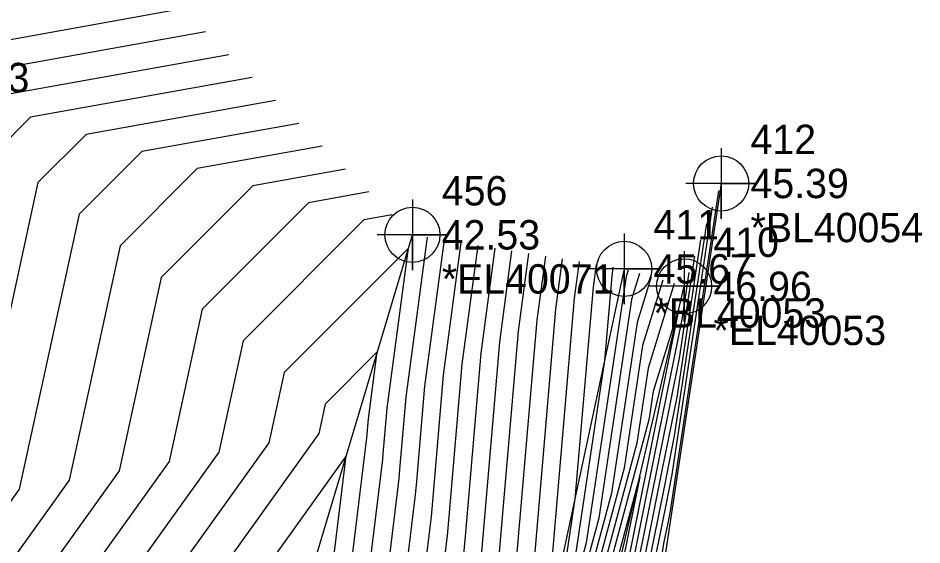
# Model space of a CAD drawing. Extents: x 2090860 to 2091277, y 159470 to 160080.
# Drawn here: x 2091069.7 to 2091146.6, y 159860.8 to 159905.6 of the extents above; entities that cross this region are included whole.
import ezdxf

# ---------------------------------------------------------------- set-up
doc = ezdxf.new("R2010")
doc.units = 0
for name, color, linetype in [('DTM Contours Major', 7, 'Continuous'), ('DTM Contours Minor', 7, 'Continuous'), ('Exist DTM Breakline', 7, 'Continuous'), ('Exist DTM Breakline Cogo Comment', 7, 'Continuous'), ('Exist DTM Breakline Cogo Elevation', 7, 'Continuous'), ('Exist DTM Breakline Cogo Number', 7, 'Continuous'), ('Exist DTM Breakline Cogo Point CELL', 7, 'Continuous'), ('Exist DTM Breakline Underwater', 7, 'Continuous'), ('Exist DTM Breakline Underwater Cogo Comment', 7, 'Continuous'), ('Exist DTM Breakline Underwater Cogo Elevation', 7, 'Continuous'), ('Exist DTM Breakline Underwater Cogo Number', 7, 'Continuous'), ('Exist DTM Breakline Underwater Cogo Point CELL', 7, 'Continuous'), ('Exist DTM Regular Point Cogo Elevation', 7, 'Continuous')]:
    doc.layers.add(name, color=color, linetype=linetype)

msp = doc.modelspace()

# ---------------------------------------------------------------- linework, layer by layer
at = {"layer": 'DTM Contours Major'}
for points in [[(2091083.646, 159906.422), (2091065.229, 159903.128), (2091061.167, 159901.876), (2091059.834, 159906.321), (2091038.544, 159901.84), (2091046.679, 159928.13)], [(2091091.582, 159898.637), (2091075.464, 159895.754), (2091071.361, 159891.649), (2091065.515, 159864.769), (2091059.162, 159855.905), (2091062.527, 159845.344), (2091062.382, 159844.528), (2091071.24, 159827.424), (2091068.468, 159817.052), (2091062.553, 159811.484), (2091060.259, 159801.479), (2091046.876, 159791.945), (2091037.586, 159782.801), (2091031.987, 159764.384), (2091026.688, 159760.214), (2091021.294, 159752.688), (2091014.874, 159747.469), (2091001.671, 159730.125), (2090998.416, 159727.263), (2090990.823, 159719.668), (2090976.25, 159706.989)], [(2091099.517, 159890.851), (2091094.379, 159889.932), (2091085.334, 159880.882), (2091082.516, 159867.927), (2091070.303, 159850.886), (2091072.441, 159844.175), (2091072.201, 159842.82), (2091077.78, 159832.047), (2091073.12, 159814.614), (2091069.924, 159811.606), (2091065.116, 159790.633), (2091059.844, 159786.877), (2091043.696, 159770.983), (2091041.123, 159762.521), (2091029.056, 159753.026), (2091026.145, 159748.964), (2091013.055, 159738.321), (2091004.963, 159727.692), (2091002.968, 159725.938), (2090989.66, 159712.626), (2090981.654, 159705.661)], [(2091122.565, 159883.928), (2091121.878, 159881.704), (2091119.096, 159863.114), (2091115.786, 159850.809), (2091115.429, 159848.821), (2091111.116, 159829.605), (2091110.193, 159820.456), (2091105.233, 159799.272), (2091103.435, 159793.012), (2091103.104, 159791.575), (2091106.385, 159784.178), (2091112.426, 159784.611), (2091120.155, 159785.157), (2091119.551, 159794.732), (2091119.607, 159802.178), (2091118.207, 159822.931), (2091118.9, 159830.534), (2091119.632, 159835.369), (2091122.895, 159856.915), (2091124.672, 159865.752), (2091125.548, 159870.109), (2091128.279, 159888.173)], [(2091105.922, 159886.774), (2091104.261, 159874.343), (2091103.538, 159865.895), (2091103.449, 159864.849), (2091101.246, 159846.776), (2091097.888, 159833.505), (2091097.32, 159832.37), (2091088.926, 159815.582), (2091086.283, 159805.672), (2091086.136, 159805.119), (2091075.366, 159785.296), (2091075.848, 159783.485), (2091075.953, 159781.891), (2091074.613, 159776.904)], [(2091111.672, 159885.85), (2091110.634, 159878.082), (2091109.134, 159860.552), (2091108.948, 159858.381), (2091107.858, 159849.436), (2091102.572, 159828.552), (2091102.265, 159827.937), (2091097.718, 159818.843), (2091092.826, 159800.504), (2091092.553, 159799.481), (2091086.279, 159787.931), (2091087.501, 159783.333), (2091087.769, 159779.288)], [(2091117.422, 159884.926), (2091117.008, 159881.82), (2091114.729, 159855.209), (2091114.539, 159852.984), (2091114.358, 159851.98), (2091113.72, 159849.137), (2091107.257, 159823.599), (2091107.21, 159823.504), (2091106.51, 159822.104), (2091099.37, 159795.336), (2091098.971, 159793.843), (2091097.192, 159790.566), (2091099.154, 159783.181), (2091099.586, 159776.685)], [(2091116.5, 159845.662), (2091116.642, 159846.45), (2091123.408, 159871.606), (2091123.751, 159873.9), (2091125.877, 159880.786), (2091124.096, 159871.932), (2091119.458, 159848.869), (2091118.165, 159840.333), (2091117.875, 159838.418), (2091116.082, 159818.747), (2091116.665, 159810.095), (2091116.541, 159793.591), (2091116.938, 159787.302), (2091111.861, 159786.943), (2091107.893, 159786.659), (2091105.739, 159791.517), (2091105.956, 159792.461), (2091110.673, 159808.884), (2091112.741, 159817.715), (2091114.792, 159838.05), (2091116.5, 159845.662)], [(2091097.594, 159868.402), (2091081.444, 159845.868), (2091082.356, 159843.007), (2091082.019, 159841.112), (2091084.319, 159836.671), (2091077.773, 159812.177), (2091077.295, 159811.727), (2091075.142, 159802.335), (2091079.718, 159810.758), (2091079.74, 159810.84), (2091080.135, 159812.321), (2091092.376, 159836.804), (2091093.203, 159838.459), (2091094.634, 159844.116), (2091097.594, 159868.402)]]:
    msp.add_lwpolyline(points, dxfattribs=at)
at = {"layer": 'DTM Contours Minor'}
for points in [[(2091085.63, 159904.476), (2091061.277, 159900.12), (2091060.882, 159899.725), (2091052.763, 159862.4), (2091050.806, 159859.669), (2091055.091, 159846.22), (2091055.018, 159845.809), (2091066.336, 159823.957), (2091064.979, 159818.88), (2091057.025, 159811.393), (2091056.616, 159809.613), (2091037.15, 159795.745), (2091033.004, 159791.665), (2091025.134, 159765.782), (2091024.911, 159765.606), (2091017.656, 159755.482), (2091016.238, 159754.329), (2090999.201, 159731.949), (2090995.001, 159728.257), (2090991.695, 159724.95), (2090972.197, 159707.986)], [(2091087.614, 159902.53), (2091066.006, 159898.665), (2091064.375, 159897.033), (2091057.014, 159863.189), (2091053.591, 159858.414), (2091057.57, 159845.928), (2091057.473, 159845.382), (2091067.971, 159825.113), (2091066.142, 159818.271), (2091058.867, 159811.424), (2091057.831, 159806.902), (2091040.392, 159794.478), (2091034.531, 159788.71), (2091027.419, 159765.316), (2091025.503, 159763.809), (2091018.868, 159754.551), (2091015.783, 159752.042), (2091000.024, 159731.341), (2090996.139, 159727.925), (2090991.404, 159723.189), (2090973.548, 159707.654)], [(2091089.598, 159900.583), (2091070.735, 159897.209), (2091067.868, 159894.341), (2091061.264, 159863.979), (2091056.377, 159857.16), (2091060.048, 159845.636), (2091059.927, 159844.955), (2091069.606, 159826.269), (2091067.305, 159817.661), (2091060.71, 159811.454), (2091059.045, 159804.19), (2091043.634, 159793.212), (2091036.059, 159785.755), (2091029.703, 159764.85), (2091026.095, 159762.012), (2091020.081, 159753.62), (2091015.328, 159749.755), (2091000.847, 159730.733), (2090997.277, 159727.594), (2090991.114, 159721.429), (2090974.899, 159707.322)], [(2091093.566, 159896.69), (2091080.192, 159894.298), (2091074.854, 159888.957), (2091069.765, 159865.558), (2091061.947, 159854.65), (2091065.005, 159845.052), (2091064.837, 159844.101), (2091072.875, 159828.58), (2091069.631, 159816.443), (2091064.396, 159811.515), (2091061.473, 159798.767), (2091050.118, 159790.678), (2091039.113, 159779.846), (2091034.271, 159763.918), (2091027.28, 159758.417), (2091022.507, 159751.757), (2091014.419, 159745.182), (2091002.494, 159729.516), (2090999.554, 159726.932), (2090990.532, 159717.907), (2090977.601, 159706.657)], [(2091095.549, 159894.744), (2091084.921, 159892.843), (2091078.348, 159886.266), (2091074.015, 159866.348), (2091064.733, 159853.396), (2091067.484, 159844.76), (2091067.291, 159843.674), (2091074.51, 159829.736), (2091070.794, 159815.833), (2091066.238, 159811.545), (2091062.688, 159796.056), (2091053.36, 159789.411), (2091040.641, 159776.892), (2091036.555, 159763.452), (2091027.872, 159756.62), (2091023.719, 159750.826), (2091013.964, 159742.895), (2091003.317, 159728.908), (2091000.692, 159726.601), (2090990.241, 159716.147), (2090978.952, 159706.325)], [(2091097.533, 159892.797), (2091089.65, 159891.387), (2091081.841, 159883.574), (2091078.266, 159867.137), (2091067.518, 159852.141), (2091069.963, 159844.468), (2091069.746, 159843.247), (2091076.145, 159830.892), (2091071.957, 159815.224), (2091068.081, 159811.575), (2091063.902, 159793.344), (2091056.602, 159788.144), (2091042.168, 159773.937), (2091038.839, 159762.987), (2091028.464, 159754.823), (2091024.932, 159749.895), (2091013.509, 159740.608), (2091004.14, 159728.3), (2091001.83, 159726.269), (2090989.951, 159714.386), (2090980.303, 159705.993)], [(2091129.277, 159890.946), (2091125.131, 159863.513), (2091124.96, 159862.663), (2091124.613, 159860.938), (2091120.366, 159832.887), (2091119.413, 159826.592), (2091119.27, 159825.023), (2091121.078, 159798.22), (2091121.056, 159795.303), (2091121.764, 159784.084), (2091112.708, 159783.445), (2091108.829, 159783.167), (2091109.089, 159778.735), (2091112.925, 159782.969), (2091122.861, 159781.908), (2091128.215, 159769.149)], [(2091121.582, 159884.214), (2091121.409, 159883.655), (2091118.018, 159860.991), (2091115.572, 159851.898), (2091115.162, 159849.611), (2091110.197, 159827.494), (2091109.557, 159821.141), (2091103.873, 159796.869), (2091102.805, 159793.15), (2091102.446, 159791.59), (2091106.008, 159783.557), (2091112.567, 159784.028), (2091120.96, 159784.62), (2091120.303, 159795.017), (2091120.342, 159800.199), (2091118.738, 159823.977), (2091119.157, 159828.563), (2091119.999, 159834.128), (2091123.754, 159858.927), (2091124.816, 159864.207), (2091125.339, 159866.811), (2091128.778, 159889.559)], [(2091101.501, 159888.904), (2091099.107, 159888.476), (2091088.827, 159878.19), (2091086.766, 159868.717), (2091073.088, 159849.632), (2091074.92, 159843.883), (2091074.655, 159842.393), (2091079.415, 159833.203), (2091074.283, 159814.005), (2091071.767, 159811.636), (2091066.33, 159787.921), (2091063.086, 159785.61), (2091045.223, 159768.028), (2091043.407, 159762.055), (2091029.648, 159751.229), (2091027.357, 159748.032), (2091012.6, 159736.034), (2091005.786, 159727.084), (2091004.106, 159725.607), (2090989.369, 159710.865), (2090983.005, 159705.329)], [(2091104.485, 159887.005), (2091102.668, 159873.409), (2091102.139, 159867.231), (2091102.074, 159866.465), (2091099.593, 159846.111), (2091096.716, 159834.744), (2091096.084, 159833.479), (2091086.728, 159814.767), (2091084.647, 159806.964), (2091084.531, 159806.529), (2091072.638, 159784.637), (2091072.934, 159783.522), (2091072.999, 159782.542), (2091072.174, 159779.473), (2091070.18, 159780.111), (2091069.897, 159779.847), (2091054.458, 159759.469)], [(2091107.36, 159886.543), (2091105.855, 159875.278), (2091104.937, 159864.559), (2091104.823, 159863.232), (2091102.899, 159847.441), (2091099.059, 159832.267), (2091098.556, 159831.262), (2091091.124, 159816.397), (2091087.919, 159804.38), (2091087.74, 159803.71), (2091078.094, 159785.955), (2091078.761, 159783.447), (2091078.907, 159781.24), (2091077.051, 159774.335)], [(2091108.797, 159886.312), (2091107.448, 159876.212), (2091106.336, 159863.224), (2091106.198, 159861.615), (2091104.552, 159848.106), (2091100.23, 159831.029), (2091099.793, 159830.154), (2091093.322, 159817.212), (2091089.555, 159803.088), (2091089.345, 159802.3), (2091080.823, 159786.614), (2091081.674, 159783.409), (2091081.861, 159780.589), (2091079.489, 159771.767)], [(2091123.547, 159883.643), (2091122.346, 159879.753), (2091120.174, 159865.237), (2091116, 159849.719), (2091115.697, 159848.031), (2091112.035, 159831.716), (2091110.83, 159819.77), (2091106.593, 159801.675), (2091104.066, 159792.874), (2091103.763, 159791.561), (2091106.762, 159784.798), (2091112.285, 159785.194), (2091119.351, 159785.693), (2091118.799, 159794.447), (2091118.871, 159804.157), (2091117.676, 159821.885), (2091118.644, 159832.505), (2091119.266, 159836.61), (2091122.035, 159854.904), (2091124.528, 159867.297), (2091125.757, 159873.407), (2091127.779, 159886.787)], [(2091068.988, 159782.281), (2091069.736, 159782.042), (2091070.045, 159783.193), (2091070.021, 159783.56), (2091069.91, 159783.978), (2091082.927, 159807.939), (2091083.011, 159808.256), (2091084.53, 159813.952), (2091094.848, 159834.587), (2091095.545, 159835.982), (2091097.94, 159845.446), (2091100.699, 159868.082), (2091100.74, 159868.566), (2091101.075, 159872.474), (2091102.892, 159886.076), (2091092.32, 159875.498), (2091091.017, 159869.506), (2091075.874, 159848.377), (2091077.398, 159843.591), (2091077.11, 159841.966), (2091081.05, 159834.359), (2091075.446, 159813.395), (2091073.609, 159811.666), (2091067.544, 159785.21)], [(2091110.235, 159886.081), (2091109.041, 159877.147), (2091107.735, 159861.888), (2091107.573, 159859.998), (2091106.205, 159848.771), (2091101.401, 159829.79), (2091101.029, 159829.046), (2091095.52, 159818.028), (2091091.191, 159801.796), (2091090.949, 159800.891), (2091083.551, 159787.272), (2091084.588, 159783.371), (2091084.815, 159779.939), (2091081.928, 159769.198)], [(2091113.11, 159885.619), (2091112.228, 159879.016), (2091110.532, 159859.216), (2091110.323, 159856.764), (2091109.511, 159850.101), (2091103.743, 159827.314), (2091103.501, 159826.829), (2091099.916, 159819.658), (2091094.462, 159799.212), (2091094.158, 159798.071), (2091089.007, 159788.59), (2091090.414, 159783.295), (2091090.724, 159778.637)], [(2091114.547, 159885.388), (2091113.821, 159879.951), (2091111.931, 159857.881), (2091111.697, 159855.147), (2091111.163, 159850.766), (2091104.915, 159826.075), (2091104.737, 159825.721), (2091102.114, 159820.473), (2091096.098, 159797.92), (2091095.762, 159796.662), (2091091.735, 159789.249), (2091093.328, 159783.257), (2091093.678, 159777.986)], [(2091124.53, 159883.357), (2091122.815, 159877.802), (2091121.252, 159867.36), (2091116.214, 159848.629), (2091115.965, 159847.242), (2091112.954, 159833.828), (2091111.467, 159819.085), (2091107.953, 159804.078), (2091104.696, 159792.737), (2091104.421, 159791.546), (2091107.139, 159785.418), (2091112.144, 159785.777), (2091118.547, 159786.229), (2091118.046, 159794.162), (2091118.136, 159806.137), (2091117.144, 159820.839), (2091118.388, 159834.476), (2091118.899, 159837.851), (2091121.176, 159852.892), (2091124.384, 159868.842), (2091125.966, 159876.706), (2091127.28, 159885.4)], [(2091115.985, 159885.157), (2091115.414, 159880.886), (2091113.33, 159856.545), (2091113.072, 159853.531), (2091112.816, 159851.431), (2091106.086, 159824.837), (2091105.974, 159824.612), (2091104.312, 159821.288), (2091097.734, 159796.628), (2091097.367, 159795.252), (2091094.463, 159789.908), (2091096.241, 159783.219), (2091096.632, 159777.335)], [(2091118.86, 159884.695), (2091118.601, 159882.755), (2091117.059, 159864.743), (2091115.862, 159856.745), (2091115.144, 159854.078), (2091114.626, 159851.19), (2091108.36, 159823.271), (2091108.283, 159822.511), (2091106.013, 159812.818), (2091101.006, 159794.044), (2091100.576, 159792.433), (2091099.92, 159791.225), (2091102.068, 159783.144), (2091102.54, 159776.034)], [(2091120.297, 159884.463), (2091120.194, 159883.689), (2091119.579, 159876.502), (2091116.94, 159858.868), (2091115.358, 159852.988), (2091114.894, 159850.4), (2091109.279, 159825.383), (2091108.92, 159821.826), (2091102.513, 159794.466), (2091102.175, 159793.287), (2091101.787, 159791.604), (2091104.122, 159786.339), (2091104.981, 159783.106), (2091105.494, 159775.383)], [(2091125.512, 159883.072), (2091123.283, 159875.851), (2091122.33, 159869.483), (2091116.428, 159847.539), (2091116.233, 159846.452), (2091113.873, 159835.939), (2091112.104, 159818.4), (2091109.313, 159806.481), (2091105.326, 159792.599), (2091105.08, 159791.532), (2091107.516, 159786.038), (2091112.003, 159786.36), (2091117.743, 159786.765), (2091117.294, 159793.876), (2091117.401, 159808.116), (2091116.613, 159819.793), (2091118.132, 159836.447), (2091118.532, 159839.092), (2091120.317, 159850.88), (2091124.24, 159870.387), (2091126.174, 159880.004), (2091126.78, 159884.014)], [(2091096.287, 159844.781), (2091099.324, 159869.699), (2091099.341, 159869.902), (2091099.482, 159871.539), (2091100.243, 159877.239), (2091095.813, 159872.807), (2091095.267, 159870.296), (2091078.659, 159847.122), (2091079.877, 159843.299), (2091079.564, 159841.539), (2091082.685, 159835.515), (2091076.609, 159812.786), (2091075.452, 159811.697), (2091070.236, 159788.941), (2091081.322, 159809.348), (2091081.375, 159809.548), (2091082.333, 159813.136), (2091093.612, 159835.695), (2091094.374, 159837.22), (2091096.287, 159844.781)], [(2091116.768, 159844.872), (2091116.856, 159845.36), (2091122.571, 159866.61), (2091118.598, 159846.857), (2091117.799, 159841.574), (2091117.619, 159840.389), (2091115.55, 159817.701), (2091115.93, 159812.075), (2091115.789, 159793.306), (2091116.134, 159787.838), (2091111.72, 159787.526), (2091108.271, 159787.279), (2091106.397, 159791.503), (2091106.586, 159792.323), (2091112.033, 159811.287), (2091113.378, 159817.03), (2091115.711, 159840.161), (2091116.768, 159844.872)]]:
    msp.add_lwpolyline(points, dxfattribs=at)
at = {"layer": 'Exist DTM Breakline'}
for points in [[(2091129.505, 159891.578), (2091119.546, 159825.567), (2091123.057, 159783.222)], [(2091121.252, 159884.31), (2091114.337, 159852.043), (2091101.513, 159791.61), (2091105.727, 159783.096)], [(2091110.781, 159791.407), (2091114.562, 159815.756), (2091117.203, 159843.59), (2091126.353, 159882.827)]]:
    msp.add_lwpolyline(points, dxfattribs=at)
at = {"layer": 'Exist DTM Breakline Cogo Point CELL'}
for points in [[(2091129.505, 159894.578), (2091129.505, 159888.578), (2091129.505, 159891.578), (2091132.505, 159891.578), (2091126.505, 159891.578)], [(2091121.252, 159887.31), (2091121.252, 159881.31), (2091121.252, 159884.31), (2091124.252, 159884.31), (2091118.252, 159884.31)], [(2091126.353, 159885.827), (2091126.353, 159879.827), (2091126.353, 159882.827), (2091129.353, 159882.827), (2091123.353, 159882.827)]]:
    msp.add_lwpolyline(points, dxfattribs=at)
for centre in [(2091129.505, 159891.578), (2091121.252, 159884.31), (2091126.353, 159882.827)]:
    msp.add_circle(centre, 2.344, dxfattribs=at)
at = {"layer": 'Exist DTM Breakline Underwater'}
msp.add_lwpolyline([(2090988.242, 159704.041), (2091010.175, 159723.841), (2091048.889, 159760.937), (2091068.273, 159783.583), (2091089.722, 159842.139), (2091103.231, 159887.207)], dxfattribs=at)
at = {"layer": 'Exist DTM Breakline Underwater Cogo Point CELL'}
msp.add_lwpolyline([(2091103.231, 159890.207), (2091103.231, 159884.207), (2091103.231, 159887.207), (2091106.231, 159887.207), (2091100.231, 159887.207)], dxfattribs=at)
msp.add_circle((2091103.231, 159887.207), 2.344, dxfattribs=at)

# ---------------------------------------------------------------- texts
at = {"layer": 'Exist DTM Breakline Cogo Comment'}
for s, p in [('*BL40054', (2091132.005, 159886.578)), ('*BL40053', (2091123.752, 159879.31)), ('*EL40053', (2091128.853, 159877.827))]:
    msp.add_text(s, height=2.5, dxfattribs=at).set_placement(p)
at = {"layer": 'Exist DTM Breakline Cogo Elevation'}
for s, p in [('45.39', (2091132.005, 159890.328)), ('45.67', (2091123.752, 159883.06)), ('46.96', (2091128.853, 159881.577))]:
    msp.add_text(s, height=2.5, dxfattribs=at).set_placement(p)
at = {"layer": 'Exist DTM Breakline Cogo Number'}
for s, p in [('412', (2091132.005, 159894.078)), ('411', (2091123.752, 159886.81)), ('410', (2091128.853, 159885.327))]:
    msp.add_text(s, height=2.5, dxfattribs=at).set_placement(p)
at = {"layer": 'Exist DTM Breakline Underwater Cogo Comment'}
msp.add_text('*EL40071', height=2.5, dxfattribs=at).set_placement((2091105.731, 159882.207))
at = {"layer": 'Exist DTM Breakline Underwater Cogo Elevation'}
msp.add_text('42.53', height=2.5, dxfattribs=at).set_placement((2091105.731, 159885.957))
at = {"layer": 'Exist DTM Breakline Underwater Cogo Number'}
msp.add_text('456', height=2.5, dxfattribs=at).set_placement((2091105.731, 159889.707))
at = {"layer": 'Exist DTM Regular Point Cogo Elevation'}
msp.add_text('44.83', height=2.5, dxfattribs=at).set_placement((2091062.264, 159899.336))

doc.saveas('drawing.dxf')
